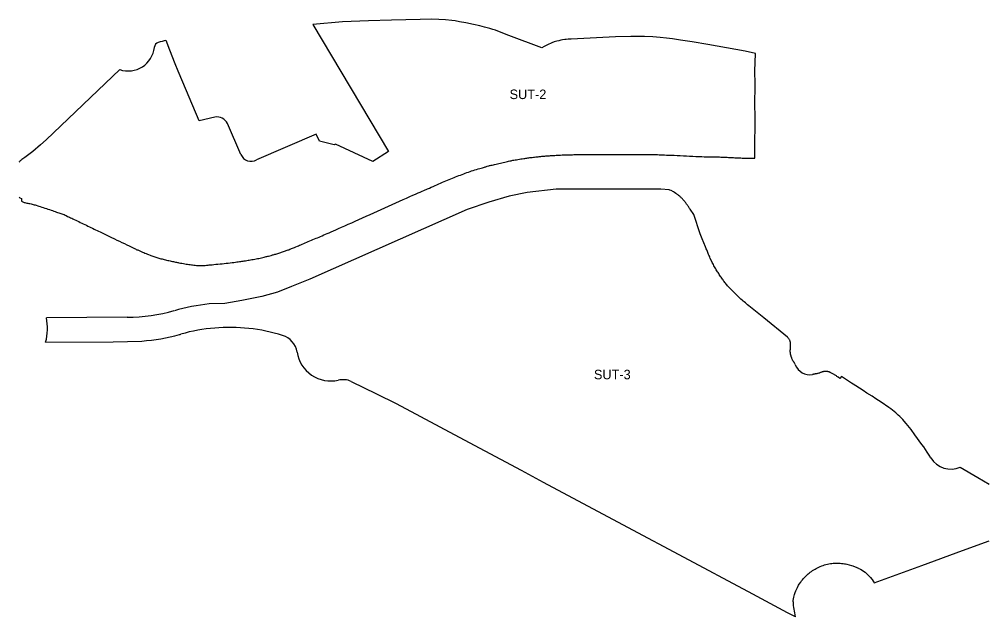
# Model space of a CAD drawing. Extents: x 428342 to 437063, y 4455780 to 4463043.
# Drawn here: x 433494 to 434509, y 4458505 to 4459132 of the extents above; entities that cross this region are included whole.
import ezdxf

# ---------------------------------------------------------------- set-up
doc = ezdxf.new("R2010")
doc.units = 0
doc.layers.add('AMB_SUS-Empresarial', color=7, linetype='Continuous')
doc.layers.add('AMB_SUS-Txt', color=7, linetype='Continuous')

msp = doc.modelspace()

# ---------------------------------------------------------------- linework, layer by layer
at = {"layer": 'AMB_SUS-Empresarial'}
for points in [[(434267.5, 4459064.4), (434267.4, 4459077.7), (434267.8, 4459096.2), (434257.2, 4459098.5), (434218, 4459105.5), (434201.6, 4459108.3), (434189.1, 4459110.2), (434180.8, 4459111.4), (434174.4, 4459112.2), (434167.8, 4459112.8), (434160.1, 4459113.5), (434151.4, 4459113.9), (434142.7, 4459114.1), (434137, 4459114.1), (434121, 4459113.5), (434074.4, 4459111.2), (434071.2, 4459111.1), (434069.1, 4459110.9), (434067.6, 4459110.7), (434065.1, 4459110.4), (434063.5, 4459110.1), (434061.5, 4459109.6), (434059.3, 4459109.1), (434056.6, 4459108.3), (434054.1, 4459107.3), (434052.5, 4459106.7), (434051, 4459106.1), (434049.3, 4459105.3), (434047.9, 4459104.6), (434045.8, 4459103.4), (434043.5, 4459102), (434008.9, 4459114.9), (433997.4, 4459119.5), (433994.7, 4459120.6), (433992.1, 4459121.4), (433988.8, 4459122.4), (433983.2, 4459123.9), (433978.2, 4459125.1), (433971.6, 4459126.6), (433963.7, 4459128.3), (433956.8, 4459129.5), (433952.4, 4459130.3), (433948.8, 4459130.8), (433942.3, 4459131.5), (433935.4, 4459131.8), (433927.7, 4459132.1), (433915.5, 4459131.9), (433885.7, 4459131.3), (433861.5, 4459130.4), (433834.1, 4459129.3), (433802.9, 4459126.6), (433882.5, 4458993.2), (433865.8, 4458982.8), (433826.8, 4459001), (433825.4, 4459000.4), (433810, 4459004.2), (433806.5, 4459011.4), (433743.8, 4458984.5)], [(433699.9, 4459029.2), (433683.6, 4459025.3), (433662.4, 4459075.3), (433661.4, 4459077.5), (433658.2, 4459085.2), (433652.6, 4459099.6), (433648.6, 4459109.8)], [(433600, 4459079.3), (433522.6, 4459005.4), (433516.7, 4459000.1), (433508.7, 4458993.4), (433500.4, 4458987.1), (433499.4, 4458986.3), (433497, 4458984.7), (433496.4, 4458984.2), (433495.7, 4458983.7), (433495.1, 4458983.1), (433494.6, 4458982.5), (433494, 4458981.9)], [(434267.4, 4458986.2), (434267.4, 4458999.2), (434267.4, 4459000), (434267.4, 4459005.3), (434267.5, 4459017.6), (434267.6, 4459031.4), (434267.4, 4459041.3), (434267.5, 4459064.4)], [(433727.3, 4458990), (433713.1, 4459022.6)], [(434304.6, 4458793), (434304.5, 4458793.5), (434304.3, 4458794.1), (434304.2, 4458794.6), (434304, 4458795.1), (434303.7, 4458795.6), (434303.4, 4458796.1), (434303.1, 4458796.6), (434302.8, 4458797), (434302.4, 4458797.4), (434301.6, 4458798.2), (434276.8, 4458818.5), (434260.9, 4458831.3), (434259.7, 4458832.2), (434258.5, 4458833.2), (434257.3, 4458834.2), (434256.2, 4458835.2), (434255, 4458836.2), (434253.8, 4458837.2), (434252.7, 4458838.2), (434251.5, 4458839.2), (434250.4, 4458840.2), (434249.3, 4458841.3), (434248.2, 4458842.3), (434246.1, 4458844.3), (434240.7, 4458849.9), (434240, 4458850.7), (434239.3, 4458851.5), (434238.6, 4458852.3), (434237.9, 4458853.2), (434237.2, 4458854), (434236.5, 4458854.8), (434235.9, 4458855.7), (434235.2, 4458856.6), (434234.5, 4458857.5), (434233.9, 4458858.3), (434233.3, 4458859.2), (434232.6, 4458860.2), (434231.9, 4458861.1), (434231.2, 4458862.1), (434230.6, 4458863.1), (434229.9, 4458864.1), (434229.3, 4458865), (434228.7, 4458866), (434228, 4458867), (434227.4, 4458868), (434226.8, 4458869), (434226.2, 4458870), (434225.6, 4458871.1), (434224.9, 4458872.2), (434224.3, 4458873.3), (434223.8, 4458874.4), (434223.2, 4458875.5), (434222.6, 4458876.6), (434222, 4458877.7), (434220.4, 4458881), (434219.9, 4458882.2), (434219.5, 4458883.2), (434219.1, 4458884.2), (434218.7, 4458885.2), (434218.3, 4458886.1), (434217.9, 4458887.1), (434217.5, 4458888.1), (434217.1, 4458889.1), (434216.7, 4458890.1), (434216.2, 4458891.1), (434215.8, 4458892.1), (434215.4, 4458893.1), (434212.1, 4458901.5), (434210, 4458906.9), (434203.1, 4458927), (434199.2, 4458932.6), (434198.7, 4458933.3), (434198.3, 4458934), (434197.8, 4458934.6), (434197.4, 4458935.3), (434196.9, 4458936), (434196.5, 4458936.7), (434196, 4458937.3), (434195.5, 4458938), (434195.1, 4458938.6), (434194.6, 4458939.3), (434194.1, 4458940), (434193.6, 4458940.6), (434193.2, 4458941.2), (434192.7, 4458941.8), (434191.7, 4458943), (434191.1, 4458943.6), (434190.6, 4458944.1), (434190, 4458944.7), (434189.5, 4458945.2), (434188.9, 4458945.8), (434188.4, 4458946.3), (434187.8, 4458946.7), (434187.2, 4458947.2), (434186.6, 4458947.6), (434186, 4458948.1), (434185.4, 4458948.5), (434184.8, 4458948.9), (434184.2, 4458949.3), (434183, 4458950.1), (434181.7, 4458950.9), (434179.4, 4458952.2), (434178, 4458952.8), (434177.3, 4458953.1), (434168.4, 4458953.7), (434128.4, 4458953.7), (434058.7, 4458953.6), (434028, 4458950.3), (434009.1, 4458946.2), (433987.9, 4458940.2), (433964.9, 4458932.2), (433799.8, 4458859), (433780.6, 4458851.3), (433765.7, 4458845.4), (433749.3, 4458840.8), (433728.3, 4458836.6), (433710.3, 4458833.7), (433694.1, 4458833.2)], [(433494.3, 4458945.3), (433494.8, 4458944.8), (433495.2, 4458944.5), (433496.7, 4458944), (433496.7, 4458941)], [(433607.9, 4458819.1), (433522.9, 4458818.6)], [(433522.1, 4458793.1), (433593, 4458793.4), (433623.3, 4458794.2)], [(434309.9, 4458769.1), (434309.5, 4458770), (434309.3, 4458770.4), (434309.1, 4458770.8), (434308.8, 4458771.2), (434308.6, 4458771.6), (434308.4, 4458772), (434308.1, 4458772.3), (434307.8, 4458772.7), (434307.6, 4458773.1), (434307.3, 4458773.5), (434306.8, 4458774.4), (434306.3, 4458775.7), (434306.1, 4458776.2), (434306, 4458776.5), (434305.9, 4458776.8), (434305.7, 4458777.2), (434305.6, 4458777.6), (434305.5, 4458778), (434305.4, 4458778.2), (434305.3, 4458778.7), (434305.2, 4458779.1), (434305.1, 4458779.3), (434305, 4458779.8), (434305, 4458779.8), (434304.9, 4458780.2), (434304.8, 4458781), (434304.6, 4458781.7), (434304.6, 4458782), (434304.5, 4458782.4), (434304.5, 4458782.8), (434304.5, 4458783.1), (434304.5, 4458783.5), (434304.5, 4458783.9), (434304.5, 4458784.2), (434304.5, 4458784.6), (434304.5, 4458785), (434304.6, 4458785.3), (434304.6, 4458785.7), (434304.9, 4458788.5)], [(434452.3, 4458671.4), (434450.4, 4458674.4), (434448.5, 4458677.3), (434446.6, 4458680.1), (434444.7, 4458682.9), (434442.7, 4458685.6), (434435.4, 4458695.7), (434431.4, 4458701.1), (434428.1, 4458705.4), (434426.4, 4458707.5), (434424.2, 4458710), (434422.7, 4458711.7), (434421.2, 4458713.3), (434419.6, 4458714.9), (434418, 4458716.4), (434415.4, 4458718.7), (434413.7, 4458720.2), (434411.9, 4458721.6), (434410.1, 4458723), (434408.2, 4458724.3), (434400, 4458729.8), (434394.3, 4458733.6), (434390.4, 4458736.2), (434385.1, 4458739.6), (434381.2, 4458742.1), (434377.2, 4458744.6), (434373.3, 4458747.2), (434370.6, 4458748.9), (434368.9, 4458750), (434358.3, 4458757), (434356.5, 4458754.7), (434354.7, 4458756.1), (434353.5, 4458757), (434353, 4458757.5), (434352.4, 4458757.9), (434351.8, 4458758.3), (434351.1, 4458758.7), (434350.5, 4458759.1), (434349.9, 4458759.5), (434349.2, 4458759.8), (434348.6, 4458760.2), (434347.9, 4458760.5), (434347.2, 4458760.9), (434346.8, 4458761.1), (434346.4, 4458761.3), (434346, 4458761.5), (434345.6, 4458761.6), (434345.2, 4458761.8), (434344.8, 4458761.9), (434344.4, 4458762), (434343.9, 4458762.1), (434343.5, 4458762.2), (434341.9, 4458762.3), (434341.5, 4458762.3), (434341, 4458762.3), (434340.6, 4458762.2), (434340.2, 4458762.2), (434339.8, 4458762.1), (434339.3, 4458762.1), (434338.9, 4458762), (434338.5, 4458761.8), (434338.1, 4458761.7), (434337.7, 4458761.6), (434337.2, 4458761.4), (434336.7, 4458761.2), (434336.2, 4458761), (434335.7, 4458760.8), (434335.2, 4458760.6), (434334.6, 4458760.4), (434333.6, 4458760.1), (434333, 4458760), (434332.5, 4458759.9), (434331.9, 4458759.8), (434331.4, 4458759.7), (434331.1, 4458759.7), (434330.8, 4458759.6), (434330.6, 4458759.6), (434330.3, 4458759.5), (434330, 4458759.5), (434329.8, 4458759.5), (434329.5, 4458759.4), (434329.2, 4458759.4), (434329, 4458759.3), (434328.5, 4458759.2), (434328, 4458759)], [(433843.1, 4458751.8), (433869.9, 4458738.7), (433890.4, 4458728.6), (433961.9, 4458690.4), (434021.7, 4458658.5), (434044.9, 4458646.1), (434138.6, 4458596), (434187.3, 4458570), (434264.7, 4458528.7), (434287.5, 4458516.5), (434301.1, 4458509.2), (434309.7, 4458504.7)], [(434513.6, 4458643.5), (434501.6, 4458650.6), (434483.1, 4458661.5)], [(434307.4, 4458520.4), (434307.7, 4458521.8), (434308, 4458523.4), (434308.4, 4458525.3), (434309.1, 4458528.1), (434309.7, 4458529.9), (434310.4, 4458531.7), (434310.8, 4458532.6), (434312, 4458535.2), (434313.3, 4458537.6), (434314, 4458538.8), (434315.6, 4458541.1), (434316.4, 4458542.2), (434317.3, 4458543.3), (434318.2, 4458544.4), (434319.1, 4458545.4), (434321.1, 4458547.6), (434323.3, 4458549.6), (434324.4, 4458550.5), (434325.5, 4458551.4), (434326.7, 4458552.3), (434328, 4458553.1), (434329.2, 4458553.9), (434330.5, 4458554.7), (434331.7, 4458555.4), (434333.2, 4458556.1), (434334.6, 4458556.8), (434336, 4458557.4), (434337.5, 4458558), (434339, 4458558.5), (434340.5, 4458559), (434342, 4458559.4), (434343.6, 4458559.8), (434345.1, 4458560.1), (434346.7, 4458560.4), (434348.2, 4458560.6), (434349.7, 4458560.8), (434351.2, 4458560.8), (434354.1, 4458560.9), (434355.6, 4458560.9), (434357, 4458560.8), (434358.5, 4458560.7), (434360, 4458560.5), (434361.4, 4458560.3), (434362.7, 4458560.1), (434364, 4458559.8), (434366.5, 4458559.2), (434368.9, 4458558.5), (434370.2, 4458558), (434372.6, 4458557.2), (434373.8, 4458556.7), (434375, 4458556.1), (434376.2, 4458555.6), (434376.5, 4458555.4), (434378.2, 4458554.5), (434379.9, 4458553.5), (434381.5, 4458552.4), (434383.1, 4458551.3), (434384.6, 4458550), (434386.1, 4458548.8), (434387.5, 4458547.4), (434388.7, 4458546), (434390.1, 4458544.2), (434390.4, 4458543.6), (434391.6, 4458542), (434392.4, 4458540.9), (434392.8, 4458540.4), (434442.8, 4458558.6), (434485.3, 4458574.1), (434513.6, 4458584.4)]]:
    msp.add_lwpolyline(points, dxfattribs=at)
for centre, radius, start, end in [((433665.8, 4459026.5), 85.1, 101.6833, 107.2956), ((433608.9, 4459105.4), 27.6, 251.1403, 354.1322), ((433642.3, 4459102), 6, 107.2956, 174.1322), ((433702.6, 4459018), 11.5, 23.4873, 103.439), ((433738, 4458994.6), 11.6, 203.194, 300.0236), ((433606.9, 4459005), 185.9, 270.3122, 285.7455), ((433718, 4458611.8), 222.6, 96.1787, 105.8057), ((433471.3, 4458807.5), 52.8, 344.1412, 12.1892), ((433715.5, 4458620), 188.5, 83.8489, 105.7455), ((433715.5, 4458620), 188.5, 72.8564, 83.8489), ((433606.9, 4459005), 211.5, 274.4413, 285.2758), ((433606.9, 4459005), 211.5, 285.2758, 285.7455), ((433764.6, 4458779.1), 22, 8.8745, 72.8564), ((434284.2, 4458789.3), 20.7, 357.7785, 10.1991), ((433821.8, 4458788.1), 35.9, 188.8745, 282.6451), ((434325, 4458775.1), 16.3, 201.2872, 280.3136), ((433834.5, 4458731.6), 22, 66.7882, 102.6451), ((434473.5, 4458684.6), 25, 211.9099, 292.721), ((434379, 4458522.6), 71.6, 181.7402, 194.4939)]:
    msp.add_arc(centre, radius, start, end, dxfattribs=at)
msp.add_open_spline([(433496.7, 4458941), (433497.9, 4458940.6), (433499, 4458940.1), (433500.1, 4458939.6), (433502.2, 4458938.8), (433504.6, 4458938.8), (433506.8, 4458938.2), (433509, 4458937.7), (433511.1, 4458937.1), (433513.2, 4458936.4), (433519.7, 4458934.4), (433526.2, 4458932.3), (433532.6, 4458930), (433537, 4458928.5), (433541.5, 4458927), (433545.7, 4458924.9), (433558.5, 4458918.8), (433571.4, 4458912.6), (433584.2, 4458906.4), (433594.5, 4458901.5), (433604.9, 4458896.5), (433615.2, 4458891.5), (433618.1, 4458890.1), (433621.1, 4458888.9), (433624, 4458887.6), (433626.5, 4458886.5), (433629, 4458885.6), (433631.5, 4458884.6), (433635.8, 4458883), (433640, 4458881.5), (433644.3, 4458880.4), (433649.2, 4458879.1), (433654.1, 4458878.1), (433659, 4458877.1), (433662.2, 4458876.4), (433665.4, 4458875.8), (433668.6, 4458875.3), (433671.2, 4458874.8), (433673.9, 4458874.5), (433676.6, 4458874.1), (433679.3, 4458873.8), (433682.1, 4458873.5), (433684.8, 4458873.5), (433688, 4458873.5), (433691.3, 4458873.8), (433694.5, 4458874.1), (433703.2, 4458875), (433711.9, 4458875.8), (433720.6, 4458876.9), (433725.8, 4458877.6), (433730.9, 4458878.3), (433736, 4458879.2), (433741.8, 4458880.1), (433747.6, 4458881.3), (433753.3, 4458882.7), (433756.2, 4458883.3), (433759.1, 4458884.1), (433762, 4458885), (433766.1, 4458886.1), (433770.1, 4458887.3), (433774.1, 4458888.8), (433777.8, 4458890.1), (433781.5, 4458891.6), (433785.1, 4458893.1), (433798.1, 4458898.6), (433811.1, 4458904.1), (433824.1, 4458909.8), (433855.2, 4458923.5), (433886.2, 4458937.7), (433917.3, 4458951.4), (433925.3, 4458954.9), (433933.2, 4458958.4), (433941.2, 4458961.8), (433947.9, 4458964.6), (433954.6, 4458967.3), (433961.4, 4458969.8), (433968, 4458972.3), (433974.8, 4458974.4), (433981.7, 4458976.4), (433984.7, 4458977.3), (433987.7, 4458978.2), (433990.8, 4458978.9), (433996.9, 4458980.4), (434003, 4458981.9), (434009.1, 4458983.1), (434011.1, 4458983.6), (434013.1, 4458984), (434015.1, 4458984.3), (434018.3, 4458984.9), (434021.4, 4458985.4), (434024.6, 4458985.9), (434026.7, 4458986.2), (434028.8, 4458986.6), (434030.9, 4458986.8), (434033.4, 4458987.1), (434035.9, 4458987.4), (434038.5, 4458987.7), (434040.5, 4458987.9), (434042.5, 4458988.1), (434044.5, 4458988.3), (434048.6, 4458988.6), (434052.7, 4458988.9), (434056.8, 4458989.1), (434063.1, 4458989.5), (434069.5, 4458989.8), (434075.8, 4458989.9), (434080.7, 4458990), (434085.6, 4458990), (434090.5, 4458990), (434101.8, 4458990.1), (434113.1, 4458990.1), (434124.4, 4458990.1), (434134.2, 4458990.1), (434144.1, 4458990.2), (434153.9, 4458990.2), (434161.2, 4458990.2), (434168.5, 4458989.8), (434175.8, 4458989.5), (434188.9, 4458989), (434202.1, 4458988.2), (434215.2, 4458987.7), (434221.2, 4458987.4), (434227.1, 4458987.6), (434233.1, 4458987.4), (434238.3, 4458987.2), (434243.5, 4458986.8), (434248.8, 4458986.6), (434251.3, 4458986.5), (434253.9, 4458986.4), (434256.4, 4458986.3), (434260.1, 4458986.3), (434263.7, 4458986.3), (434267.4, 4458986.2)], degree=3, dxfattribs=at)

# ---------------------------------------------------------------- texts
at = {"layer": 'AMB_SUS-Txt'}
for s, p in [('SUT-2', (434009.6, 4459048.3)), ('SUT-3', (434098.2, 4458754))]:
    msp.add_text(s, height=10, dxfattribs=at).set_placement(p)

doc.saveas('drawing.dxf')
